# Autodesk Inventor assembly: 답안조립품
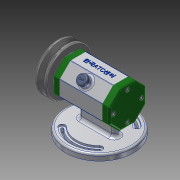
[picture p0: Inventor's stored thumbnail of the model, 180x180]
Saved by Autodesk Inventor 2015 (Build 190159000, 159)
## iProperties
Created: 2017-06
Part Number: 답안조립품
Document SubType Name: Assembly
Designer: user
Author: user
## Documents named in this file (14)
- C:\Users\user\Desktop\470607V1001\답안조립품.iam
- C:\Users\user\Desktop\470607V1001\본체.ipt
- C:\Users\user\Desktop\470607V1001\고무캡.ipt
- C:\Users\user\Desktop\470607V1001\축.ipt
- C:\Users\user\Desktop\470607V1001\베어링 15 x 32 x 9.ipt
- C:\Users\user\Desktop\470607V1001\뒤커버.ipt
- C:\Users\user\Desktop\470607V1001\앞커버.ipt
- C:\Users\user\Desktop\470607V1001\오일 실 15 25 7.ipt
- C:\Users\user\Desktop\470607V1001\키 3 x 3 x 12.ipt
- C:\Users\user\Desktop\470607V1001\볼트 M4 x 12.ipt
- C:\Users\user\Desktop\470607V1001\V벨트풀리.ipt
- C:\Users\user\Desktop\470607V1001\와셔 8x17.ipt
- C:\Users\user\Desktop\470607V1001\스프링와셔 8.ipt
- C:\Users\user\Desktop\470607V1001\너트 M 8.ipt
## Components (2 placed, 2 different names)
1. 고무캡:1 — 각도:1
2. V벨트풀리:1
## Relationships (1: Angle 1)
- 각도:1 [Angle]: 고무캡:1
